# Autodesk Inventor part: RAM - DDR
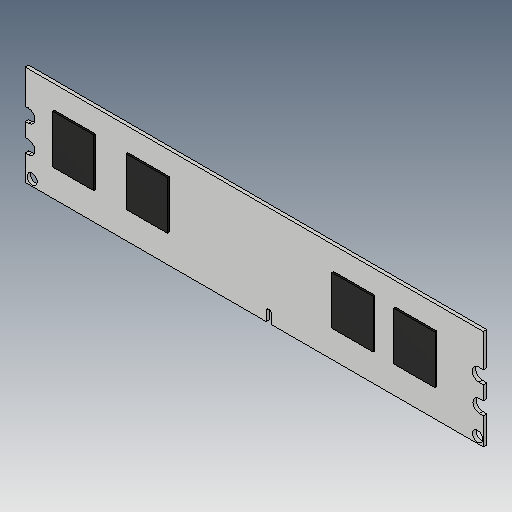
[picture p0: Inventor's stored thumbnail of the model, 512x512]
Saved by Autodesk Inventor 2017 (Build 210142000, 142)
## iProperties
Created: 2005-12
Part Number: RAM - DDR
Material: Generic
Document SubType Name: Modeling
Designer: DanielSeverino
Density: 1 g/cm^3
Appearance: Default
Author: DanielSeverino
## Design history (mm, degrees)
feature "Solid1"
body "Solid2"
